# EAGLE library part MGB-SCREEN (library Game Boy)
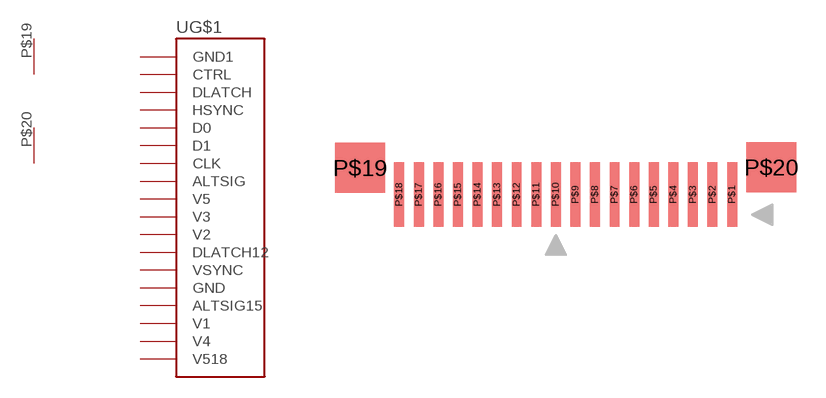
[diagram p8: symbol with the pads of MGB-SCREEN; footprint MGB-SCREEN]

Designator prefix -; gates G$1=MGB-SCREEN G$2=PWRGND G$3=PWRGND

## MGB-SCREEN  [MGB-SCREEN]
P$1  G$1:GND1
P$2  G$1:CTRL
P$3  G$1:DLATCH
P$4  G$1:HSYNC
P$5  G$1:D0
P$6  G$1:D1
P$7  G$1:CLK
P$8  G$1:ALTSIG
P$9  G$1:V5
P$10  G$1:V3
P$11  G$1:V2
P$12  G$1:DLATCH12
P$13  G$1:VSYNC
P$14  G$1:GND
P$15  G$1:ALTSIG15
P$16  G$1:V1
P$17  G$1:V4
P$18  G$1:V518
P$19  G$2:GND  pwr
P$20  G$3:GND  pwr

## Footprint MGB-SCREEN (pad centres in mm)
smd 0.508 x 3.302: P$1 8.5,0; P$2 7.5,0; P$3 6.5,0; P$4 5.5,0; P$5 4.5,0; P$6 3.5,0; P$7 2.5,0; P$8 1.5,0; P$9 0.5,0; P$10 -0.5,0; P$11 -1.5,0; P$12 -2.5,0; P$13 -3.5,0; P$14 -4.5,0; P$15 -5.5,0; P$16 -6.5,0; P$17 -7.5,0; P$18 -8.5,0
smd 2.54 x 2.54: P$19 -10.5,1.367; P$20 10.5,1.397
